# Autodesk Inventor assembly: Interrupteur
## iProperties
Created: 2002-05
Part Number: Interrupteur
Document SubType Name: Assemblage
Designer: Flavien MARTY
Control State: 0
Master: False
Checked Out: False
Shininess: 41.0
Length Units: 11269
Angle Units: 11279
Time Units: 11290
Mass Units: 11283
Length Display Precision: 3
Angle Display Precision: 2
Density: 0.0
Volumn: 0.0
Area: 0.0
PropertySet Name: Model Information
Author: Flavien MARTY
